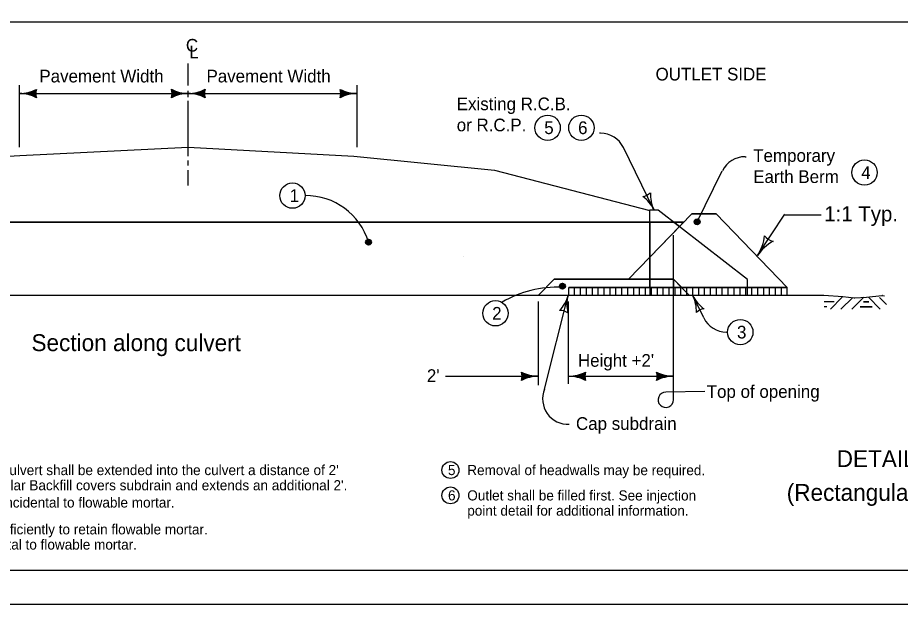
# Model space of a CAD drawing. Extents: x 10133 to 81668, y 7924 to 11018.
# Drawn here: x 11172 to 12218, y 7924 to 8619 of the extents above; entities that cross this region are included whole.
import ezdxf

# ---------------------------------------------------------------- set-up
doc = ezdxf.new("R2010")
doc.units = 0
for name, color, linetype in [('dsnCellElements', 7, 'Continuous'), ('Level 10', 7, 'Continuous'), ('Level 12', 7, 'Continuous'), ('SheetAddendum', 7, 'Continuous'), ('SheetBorder', 7, 'Continuous'), ('ShtPlotIdentification', 7, 'Continuous')]:
    doc.layers.add(name, color=color, linetype=linetype)

msp = doc.modelspace()

# ---------------------------------------------------------------- linework, layer by layer
at = {"layer": 'dsnCellElements'}
for p, q in [((11373.8, 8538.5), (11373.8, 8564.6)), ((11173.8, 8465.5), (11173.8, 8539.1)), ((11573.8, 8465.5), (11573.8, 8539.1)), ((11173.8, 8529.1), (11193, 8529.1)), ((11173.8, 8529.1), (11373.8, 8529.1)), ((11373.9, 8529.2), (11354.7, 8529.2)), ((11373.7, 8529.2), (11392.9, 8529.2)), ((11373.8, 8525), (11373.8, 8532.4)), ((11373.8, 8529.1), (11573.8, 8529.1)), ((11573.8, 8529.1), (11554.6, 8529.1)), ((11373.8, 8454.9), (11373.8, 8520.4)), ((11862.4, 8482), (11861.1, 8482)), ((11174.4, 8455.9), (11373.7, 8465.6)), ((11373.7, 8465.6), (11569.9, 8454.8)), ((11925.6, 8391.4), (11889.4, 8465.3)), ((11005.8, 8444.1), (11174.4, 8455.9)), ((11569.9, 8454.8), (11736.7, 8438.2)), ((12033.6, 8454.3), (12034.9, 8454.3)), ((11373.8, 8444), (11373.8, 8449.8)), ((11373.8, 8420.3), (11373.8, 8438.2)), ((11736.7, 8438.2), (11920.8, 8390.7)), ((11976.1, 8375.4), (12006.6, 8437.6)), ((11920.8, 8391.4), (11930.5, 8391.4)), ((11920.8, 8376.7), (11920.8, 8391.4)), ((11930.5, 8391.3), (12036.5, 8309.1)), ((11895.6, 8309.3), (11970.3, 8386.7)), ((11970.3, 8386.7), (11999.4, 8386.7)), ((12083.6, 8299.5), (11999.4, 8386.7)), ((12048.4, 8337.3), (12080.6, 8386.2)), ((12080, 8385.3), (12123.6, 8385.4)), ((10786.9, 8376.7), (11949.3, 8376.7)), ((11920.8, 8376.7), (11920.8, 8290.1)), ((11949.2, 8376.8), (11960.7, 8376.8)), ((11948.7, 8166.4), (11948.7, 8361.4)), ((11788.7, 8290.1), (11807.3, 8309.3)), ((11807.3, 8309.3), (11948.7, 8309.3)), ((11967.3, 8290.1), (11948.7, 8309.3)), ((12036.4, 8290.1), (12036.4, 8309)), ((10642.2, 8290.1), (12126.8, 8290.1)), ((11796, 8178.9), (11823.9, 8290.1)), ((11984.7, 8263.3), (11971.6, 8290)), ((12126.8, 8290.1), (12149.3, 8288.7)), ((12148.8, 8287.9), (12134.7, 8273.8)), ((12161.3, 8287.7), (12147.1, 8273.6)), ((12149.5, 8288.7), (12162.7, 8287.3)), ((12174.3, 8287.9), (12160.1, 8273.8)), ((12163.5, 8287.3), (12177.3, 8287.9)), ((12177.6, 8288), (12195.5, 8289.7)), ((12179.7, 8287.9), (12193.8, 8273.8)), ((12192.7, 8287.7), (12201.2, 8279.2)), ((12196.3, 8289.7), (12198.9, 8289.5)), ((11788.7, 8183.6), (11788.7, 8282.9)), ((11824.5, 8185.2), (11824.5, 8282.9)), ((12139.2, 8282.4), (12127.2, 8282.4)), ((12130.5, 8276.6), (12127.2, 8276.6)), ((12130.5, 8276.6), (12130.5, 8276.6)), ((12136.3, 8282.4), (12136.3, 8282.4)), ((12184.1, 8276.6), (12169.9, 8276.6)), ((12169.9, 8276.6), (12184.1, 8276.6)), ((12180.3, 8282.4), (12173.7, 8282.4)), ((12173.7, 8282.4), (12180.3, 8282.4)), ((11678.6, 8194.2), (11788.5, 8194.2)), ((11788.5, 8194.2), (11769.3, 8194.2)), ((11824.5, 8194.2), (11843.7, 8194.2)), ((11824.5, 8194.2), (11948.7, 8194.2)), ((11948.7, 8194.2), (11929.5, 8194.2)), ((11985.8, 8176.1), (11939.6, 8175.5)), ((11801.2, 8147.6), (11802.1, 8146.6))]:
    msp.add_line(p, q, dxfattribs=at)
for points in [[(11192.6, 8525.6), (11191.9, 8529.1), (11192.6, 8532.7), (11188.3, 8530.7), (11181.5, 8529.1), (11188.8, 8527.4), (11192, 8526), (11191.2, 8529.1), (11191.5, 8531.4), (11188.7, 8530.1), (11184.9, 8529.1), (11188.9, 8528), (11191, 8527.2), (11190.6, 8530.3), (11187.9, 8529.1), (11190, 8528.4), (11190.1, 8529.5), (11189.1, 8529.2)], [(11355.1, 8532.7), (11355.8, 8529.1), (11355.1, 8525.5), (11359.4, 8527.6), (11366.2, 8529.1), (11358.9, 8530.8), (11355.7, 8532.3), (11356.5, 8529.1), (11356.2, 8526.8), (11359, 8528.2), (11362.8, 8529.1), (11358.8, 8530.3), (11356.7, 8531), (11357.1, 8528), (11359.9, 8529.1), (11357.7, 8529.8), (11357.6, 8528.8), (11358.7, 8529.1)], [(11392.5, 8525.6), (11391.8, 8529.2), (11392.6, 8532.8), (11388.3, 8530.7), (11381.5, 8529.2), (11388.8, 8527.5), (11391.9, 8526.1), (11391.2, 8529.2), (11391.5, 8531.5), (11388.6, 8530.2), (11384.9, 8529.2), (11388.9, 8528), (11391, 8527.3), (11390.6, 8530.4), (11387.8, 8529.2), (11390, 8528.5), (11390, 8529.6), (11389, 8529.2)], [(11554.9, 8532.7), (11555.7, 8529.1), (11554.9, 8525.5), (11559.2, 8527.6), (11566, 8529.1), (11558.7, 8530.8), (11555.5, 8532.2), (11556.3, 8529.1), (11556, 8526.8), (11558.9, 8528.1), (11562.6, 8529.1), (11558.6, 8530.3), (11556.5, 8531), (11556.9, 8527.9), (11559.7, 8529.1), (11557.5, 8529.8), (11557.5, 8528.7), (11558.5, 8529.1)], [(11977, 8380.3), (11975.8, 8379.8), (11974, 8379.2), (11973.6, 8377.3), (11973.8, 8375.7), (11975, 8374.2), (11976.8, 8374.3), (11978.6, 8374.6), (11979.5, 8376.1), (11979.7, 8377.6), (11978.6, 8379.6), (11977.2, 8379.8), (11975.4, 8379.3), (11973.9, 8378.2), (11973.9, 8376.4), (11975.1, 8375), (11976.8, 8374.8), (11978.6, 8375.2), (11978.9, 8376.2), (11979.3, 8377.5), (11978.4, 8379), (11977, 8379), (11975.5, 8378.7), (11974.4, 8377.9), (11975, 8376.3), (11976.1, 8375.4), (11977.7, 8375.4), (11978.1, 8376.2), (11978.5, 8377.2), (11977.8, 8378.4), (11976.6, 8378.6), (11975.6, 8378.1), (11975.6, 8377), (11976.1, 8376.2), (11977.1, 8375.9), (11977.6, 8376.3), (11977.9, 8376.9), (11977.4, 8377.8), (11976.7, 8378), (11976, 8377.6), (11976.1, 8377), (11976.6, 8376.6), (11977.3, 8376.6), (11977.3, 8377.1), (11976.7, 8377.4)], [(11587.7, 8356.2), (11586.5, 8355.7), (11584.6, 8355.1), (11584.3, 8353.2), (11584.5, 8351.6), (11585.7, 8350.1), (11587.5, 8350.2), (11589.3, 8350.5), (11590.2, 8352), (11590.4, 8353.5), (11589.3, 8355.5), (11587.9, 8355.7), (11586.1, 8355.2), (11584.6, 8354.1), (11584.6, 8352.3), (11585.8, 8350.9), (11587.4, 8350.7), (11589.3, 8351.1), (11589.6, 8352.1), (11589.9, 8353.4), (11589.1, 8354.9), (11587.7, 8354.9), (11586.2, 8354.6), (11585.1, 8353.8), (11585.7, 8352.2), (11586.8, 8351.3), (11588.4, 8351.3), (11588.7, 8352.1), (11589.2, 8353.1), (11588.5, 8354.3), (11587.3, 8354.6), (11586.3, 8354), (11586.3, 8352.9), (11586.8, 8352.1), (11587.8, 8351.8), (11588.3, 8352.2), (11588.6, 8352.8), (11588.1, 8353.7), (11587.4, 8353.9), (11586.6, 8353.5), (11586.8, 8352.9), (11587.3, 8352.5), (11588, 8352.5), (11588, 8353), (11587.4, 8353.3)], [(11817.4, 8304.1), (11816.2, 8303.5), (11814.3, 8303), (11814, 8301.1), (11814.2, 8299.5), (11815.4, 8298), (11817.2, 8298.1), (11819, 8298.4), (11819.9, 8299.8), (11820.1, 8301.4), (11819, 8303.4), (11817.6, 8303.6), (11815.8, 8303.1), (11814.3, 8301.9), (11814.3, 8300.2), (11815.5, 8298.8), (11817.2, 8298.6), (11819, 8299), (11819.3, 8300), (11819.6, 8301.3), (11818.8, 8302.8), (11817.4, 8302.8), (11815.9, 8302.5), (11814.8, 8301.7), (11815.4, 8300.1), (11816.5, 8299.2), (11818.1, 8299.2), (11818.4, 8300), (11818.9, 8301), (11818.2, 8302.2), (11817, 8302.4), (11816, 8301.9), (11816, 8300.8), (11816.5, 8300), (11817.5, 8299.7), (11818, 8300.1), (11818.3, 8300.7), (11817.8, 8301.6), (11817.1, 8301.8), (11816.4, 8301.4), (11816.5, 8300.8), (11817, 8300.4), (11817.7, 8300.4), (11817.7, 8300.9), (11817.1, 8301.2)], [(11769.7, 8197.7), (11770.4, 8194.2), (11769.6, 8190.6), (11773.9, 8192.6), (11780.8, 8194.2), (11773.4, 8195.9), (11770.3, 8197.3), (11771.1, 8194.2), (11770.8, 8191.8), (11773.6, 8193.2), (11777.4, 8194.2), (11773.3, 8195.3), (11771.2, 8196.1), (11771.6, 8193), (11774.4, 8194.2), (11772.2, 8194.9), (11772.2, 8193.8), (11773.2, 8194.1)], [(11843.3, 8190.7), (11842.6, 8194.3), (11843.3, 8197.9), (11839, 8195.8), (11832.2, 8194.3), (11839.6, 8192.5), (11842.7, 8191.1), (11841.9, 8194.3), (11842.2, 8196.6), (11839.4, 8195.2), (11835.6, 8194.3), (11839.7, 8193.1), (11841.8, 8192.4), (11841.4, 8195.4), (11838.6, 8194.3), (11840.8, 8193.6), (11840.8, 8194.6), (11839.8, 8194.3)], [(11929.9, 8197.7), (11930.6, 8194.2), (11929.9, 8190.6), (11934.2, 8192.6), (11941, 8194.2), (11933.6, 8195.9), (11930.5, 8197.3), (11931.3, 8194.2), (11931, 8191.8), (11933.8, 8193.2), (11937.6, 8194.2), (11933.6, 8195.3), (11931.5, 8196.1), (11931.8, 8193), (11934.6, 8194.2), (11932.4, 8194.9), (11932.4, 8193.8), (11933.4, 8194.1)]]:
    msp.add_lwpolyline(points, dxfattribs=at)
for centre, radius in [((11799.6, 8488.6), 15), ((11839.6, 8488.6), 15), ((12175.1, 8435.5), 15), ((11497.3, 8408.2), 15), ((11976.7, 8377.1), 3.5), ((11587.4, 8353), 3.5), ((11817.1, 8300.9), 3.5), ((11737.8, 8268.8), 15), ((12027.9, 8246.5), 15), ((11684.4, 8083.1), 10), ((11684.4, 8053.1), 10)]:
    msp.add_circle(centre, radius, dxfattribs=at)
for centre, radius, start, end in [((11173.8, 8571.6), 42.5, 270, 298.0725), ((11173.8, 8486.6), 42.5, 61.9275, 90), ((11209.4, 8529.1), 16.4, 162.2666, 197.7334), ((11338.3, 8529.2), 16.4, 342.2666, 17.7334), ((11373.9, 8571.7), 42.5, 241.9275, 270), ((11373.9, 8486.7), 42.5, 90, 118.0725), ((11373.7, 8571.7), 42.5, 270, 298.0725), ((11373.7, 8486.7), 42.5, 61.9275, 90), ((11409.4, 8529.2), 16.4, 162.2666, 197.7334), ((11538.1, 8529.1), 16.4, 342.2666, 17.7334), ((11573.8, 8571.6), 42.5, 241.9275, 270), ((11573.8, 8486.6), 42.5, 90, 118.0725), ((11862.4, 8452), 30, 26.1599, 90), ((12033.6, 8424.3), 30, 90, 153.8397), ((11909.9, 8423.4), 16.4, 278.427, 313.8937), ((11963.8, 8410.2), 42.5, 178.0879, 206.1604), ((11513.3, 8331), 77.2, 16.5237, 90.8016), ((11887.5, 8372.7), 42.5, 26.1604, 54.2328), ((12005.6, 8365.4), 51.2, 326.6555, 354.7279), ((12072, 8373.1), 19.8, 218.9221, 254.3888), ((12091.2, 8309.1), 51.2, 118.583, 146.6555), ((11811.2, 8171), 128.8, 87.6655, 120.5189), ((11782.8, 8301.1), 42.5, 316.8529, 344.9253), ((11864.9, 8279), 42.5, 164.9253, 192.9978), ((11933.4, 8271.2), 42.5, 358.0872, 26.1597), ((12009.7, 8308.7), 42.5, 206.1597, 234.2322), ((12149, 8283.7), 5, 84.0146, 86.4551), ((12163.2, 8292.2), 5, 264.0146, 272.8473), ((12177.1, 8292.9), 5, 272.8473, 275.5382), ((12195.9, 8284.7), 5, 85.9429, 95.5382), ((11987.3, 8258), 16.4, 98.4264, 133.8931), ((11814.6, 8255.7), 16.4, 57.192, 92.6587), ((12011.6, 8276.5), 30, 206.1604, 270), ((11752.9, 8194.2), 16.4, 342.2666, 17.7334), ((11788.5, 8236.7), 42.5, 241.9275, 270), ((11788.5, 8151.7), 42.5, 90, 118.0725), ((11824.5, 8236.7), 42.5, 270, 298.0725), ((11824.5, 8151.7), 42.5, 61.9275, 90), ((11860.1, 8194.2), 16.4, 162.2666, 197.7334), ((11913.1, 8194.2), 16.4, 342.2666, 17.7334), ((11948.7, 8236.7), 42.5, 241.9275, 270), ((11948.7, 8151.7), 42.5, 90, 118.0725), ((11823.7, 8167.4), 30, 157.6234, 272.9348)]:
    msp.add_arc(centre, radius, start, end, dxfattribs=at)
at = {"layer": 'Level 10'}
for p, q in [((11824.6, 8290), (11824.6, 8299.5)), ((12083.6, 8299.5), (11824.6, 8299.5)), ((11831.6, 8290), (11831.6, 8299.5)), ((11838.6, 8290), (11838.6, 8299.5)), ((11845.6, 8290), (11845.6, 8299.5)), ((11852.6, 8290), (11852.6, 8299.5)), ((11859.6, 8290), (11859.6, 8299.5)), ((11866.6, 8290), (11866.6, 8299.5)), ((11873.6, 8290), (11873.6, 8299.5)), ((11880.6, 8290), (11880.6, 8299.5)), ((11887.6, 8290), (11887.6, 8299.5)), ((11894.6, 8290), (11894.6, 8299.5)), ((11901.6, 8290), (11901.6, 8299.5)), ((11908.6, 8290), (11908.6, 8299.5)), ((11915.6, 8290), (11915.6, 8299.5)), ((11922.6, 8290), (11922.6, 8299.5)), ((11929.6, 8290), (11929.6, 8299.5)), ((11936.6, 8290), (11936.6, 8299.5)), ((11943.6, 8290), (11943.6, 8299.5)), ((11950.6, 8290), (11950.6, 8299.5)), ((11957.6, 8290), (11957.6, 8299.5)), ((11964.6, 8290), (11964.6, 8299.5)), ((11971.6, 8290), (11971.6, 8299.5)), ((11978.6, 8290), (11978.6, 8299.5)), ((11985.6, 8290), (11985.6, 8299.5)), ((11992.6, 8290), (11992.6, 8299.5)), ((11999.6, 8290), (11999.6, 8299.5)), ((12006.6, 8290), (12006.6, 8299.5)), ((12013.6, 8290), (12013.6, 8299.5)), ((12020.6, 8290), (12020.6, 8299.5)), ((12027.6, 8290), (12027.6, 8299.5)), ((12034.6, 8290), (12034.6, 8299.5)), ((12041.6, 8290), (12041.6, 8299.5)), ((12048.6, 8290), (12048.6, 8299.5)), ((12055.6, 8290), (12055.6, 8299.5)), ((12062.6, 8290), (12062.6, 8299.5)), ((12069.6, 8290), (12069.6, 8299.5)), ((12076.6, 8290), (12076.6, 8299.5)), ((12083.6, 8290), (12083.6, 8299.5))]:
    msp.add_line(p, q, dxfattribs=at)
at = {"layer": 'Level 12'}
msp.add_lwpolyline([(10147.5, 8614), (13252.5, 8614), (13252.5, 7964), (10147.5, 7964), (10147.5, 8614)], dxfattribs=at)
for points in [[(12083.6, 8299.5), (12083.6, 8299.5), (11999.4, 8386.7), (11970.3, 8386.7), (11920.8, 8335.4), (11920.8, 8309.3), (11948.7, 8309.3), (11958.2, 8299.5)], [(11920.8, 8335.4), (11920.8, 8376.7), (10811.4, 8376.7), (10811.4, 8351.4), (10870.5, 8290.1), (11788.7, 8290.1), (11807.3, 8309.3), (11895.6, 8309.3)], [(11955.8, 8371.7), (11949.3, 8376.7), (11920.8, 8376.7), (11920.8, 8335.4)], [(11960.7, 8376.8), (11949.2, 8376.8), (11955.8, 8371.7)], [(11920.8, 8309.3), (11920.8, 8335.4), (11895.6, 8309.3)], [(11920.8, 8309.3), (11807.3, 8309.3), (11788.7, 8290.1), (11824.6, 8290.1), (11824.6, 8299.5), (11920.8, 8299.5)], [(11948.7, 8299.5), (11948.7, 8309.3), (11920.8, 8309.3), (11920.8, 8299.5)], [(11958.2, 8299.5), (11948.7, 8309.3), (11948.7, 8299.5)]]:
    msp.add_lwpolyline(points, close=True, dxfattribs=at)
for centre in [(11976.7, 8377.1), (11587.4, 8353)]:
    msp.add_circle(centre, 3.5, dxfattribs=at)
at = {"layer": 'SheetAddendum'}
msp.add_line((11700, 8336.5), (11700, 8336.5), dxfattribs=at)
msp.add_arc((11939.6, 8166.4), 9.1, 90, 0.0003, dxfattribs=at)
at = {"layer": 'SheetBorder'}
msp.add_lwpolyline([(10132.5, 9944), (13267.5, 9944), (13267.5, 7924), (10132.5, 7924)], close=True, dxfattribs=at)

# ---------------------------------------------------------------- texts
at = {"layer": 'dsnCellElements'}
msp.add_text('1:1 Typ.', height=18.09, dxfattribs=at).set_placement((12127.4, 8377.6))
at = {"layer": 'ShtPlotIdentification'}
for s, height, p in [('C', 15, (11371, 8578.8)), ('L', 15, (11375, 8570.9)), ('1', 15, (11493.9, 8400.7)), ('2', 15, (11733.9, 8261.3)), ('3', 15, (12024, 8239)), ('Cap subdrain', 15, (11833.2, 8130.7)), ('DETAILS OF CULVERT ABANDONMENT WITH FLOWABLE MORTAR ', 20, (12142.1, 8086.6)), ('4" subdrain at flowline elevation of culvert shall be extended into the culvert a distance of 2\'  ', 12, (10906.4, 8077.1)), ("plus the height of the culvert. Granular Backfill covers subdrain and extends an additional 2'.", 12, (10909, 8059.1)), ("(Rectangular structures less than 8' in either height or width. ", 20, (12082.9, 8046.6)), ('Subdrain and granular backfill are incidental to flowable mortar.', 12, (10909, 8038.7))]:
    msp.add_text(s, height=height, dxfattribs=at).set_placement(p)
for s, height, rotation, p in [('Pavement Width', 15, 359.9814, (11197.4, 8542.3)), ('Pavement Width', 15, 359.9814, (11395.4, 8542.3)), ('OUTLET SIDE', 15, 0.0185, (11927.5, 8544.6)), ('Existing R.C.B. ', 15, 359.9819, (11691.9, 8509.4)), ('or R.C.P.', 15, 359.9819, (11691.9, 8484.4)), ('5', 15, 359.9815, (11795.6, 8481.1)), ('6', 15, 359.9815, (11835.7, 8481.1)), ('Temporary ', 15, 359.9815, (12043.2, 8448.2)), ('4', 15, 359.9815, (12171.2, 8428)), ('Earth Berm', 15, 359.9815, (12043.2, 8423.2)), ('Section along culvert', 20, 359.9815, (11188, 8224)), ("Height +2'", 15, 359.9814, (11835.5, 8205.5)), ("2'", 15, 359.9814, (11656.5, 8187.5)), ('Top of opening', 15, 0.0185, (11988.1, 8168.6)), ('5', 12, 359.9815, (11681.5, 8077.1)), ('Removal of headwalls may be required.', 12, 359.9815, (11704.4, 8077.1)), ('6', 12, 359.9815, (11681.6, 8047.1)), ('Outlet shall be filled first. See injection ', 12, 359.9815, (11704.4, 8047.1)), ('point detail for additional information.', 12, 359.9815, (11704.4, 8029.1)), ('Ends of culvert shall be plugged sufficiently to retain flowable mortar.', 12, 359.9815, (10909, 8007)), ('Temporary earth berms are incidental to flowable mortar.', 12, 359.9815, (10909, 7989))]:
    msp.add_text(s, height=height, rotation=rotation, dxfattribs=at).set_placement(p)

doc.saveas('drawing.dxf')
